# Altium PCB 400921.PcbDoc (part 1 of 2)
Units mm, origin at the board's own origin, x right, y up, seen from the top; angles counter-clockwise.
Board outline 33 x 32.99 mm, 4 copper layers (Top Layer, Mid-Layer 1, Mid-Layer 2, Bottom Layer), stack 0.75 mm thick; 113 components, 68 nets, 329 pads, 369 vias.
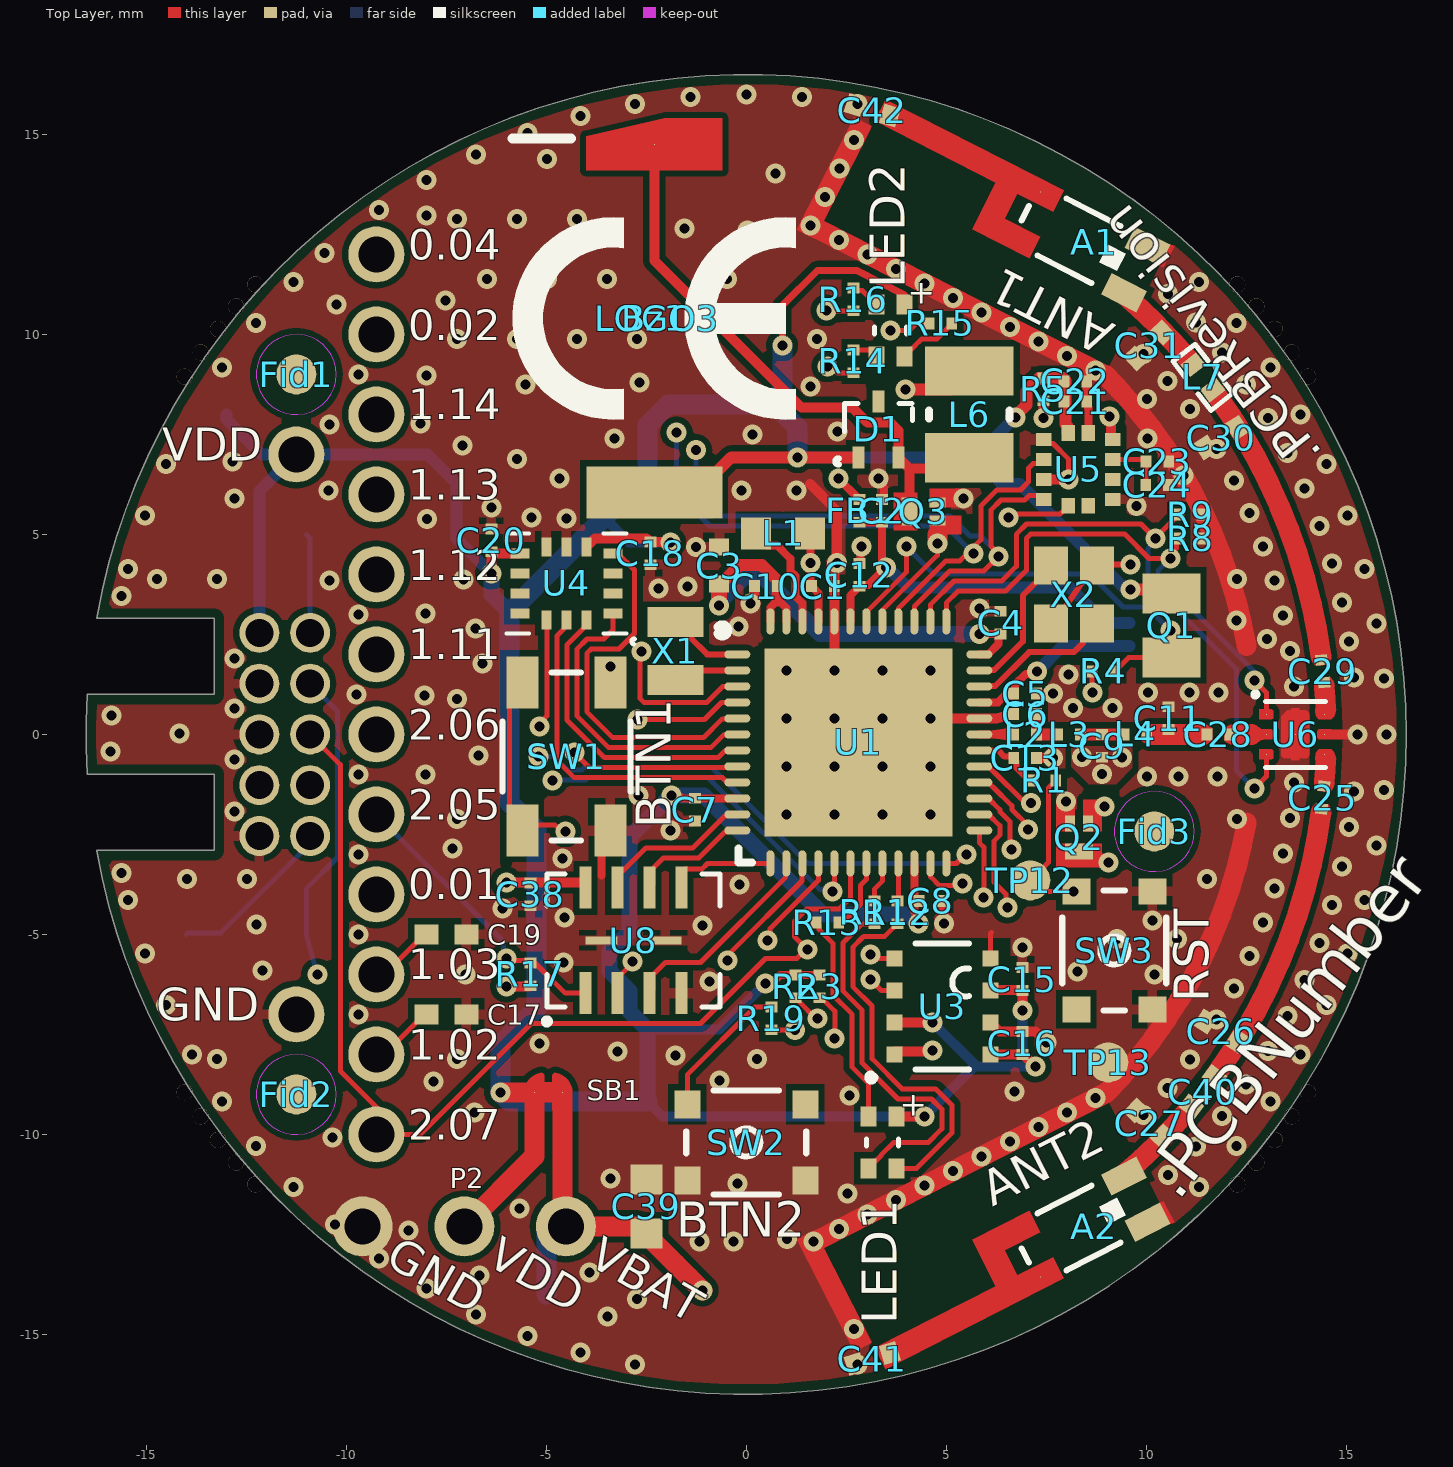
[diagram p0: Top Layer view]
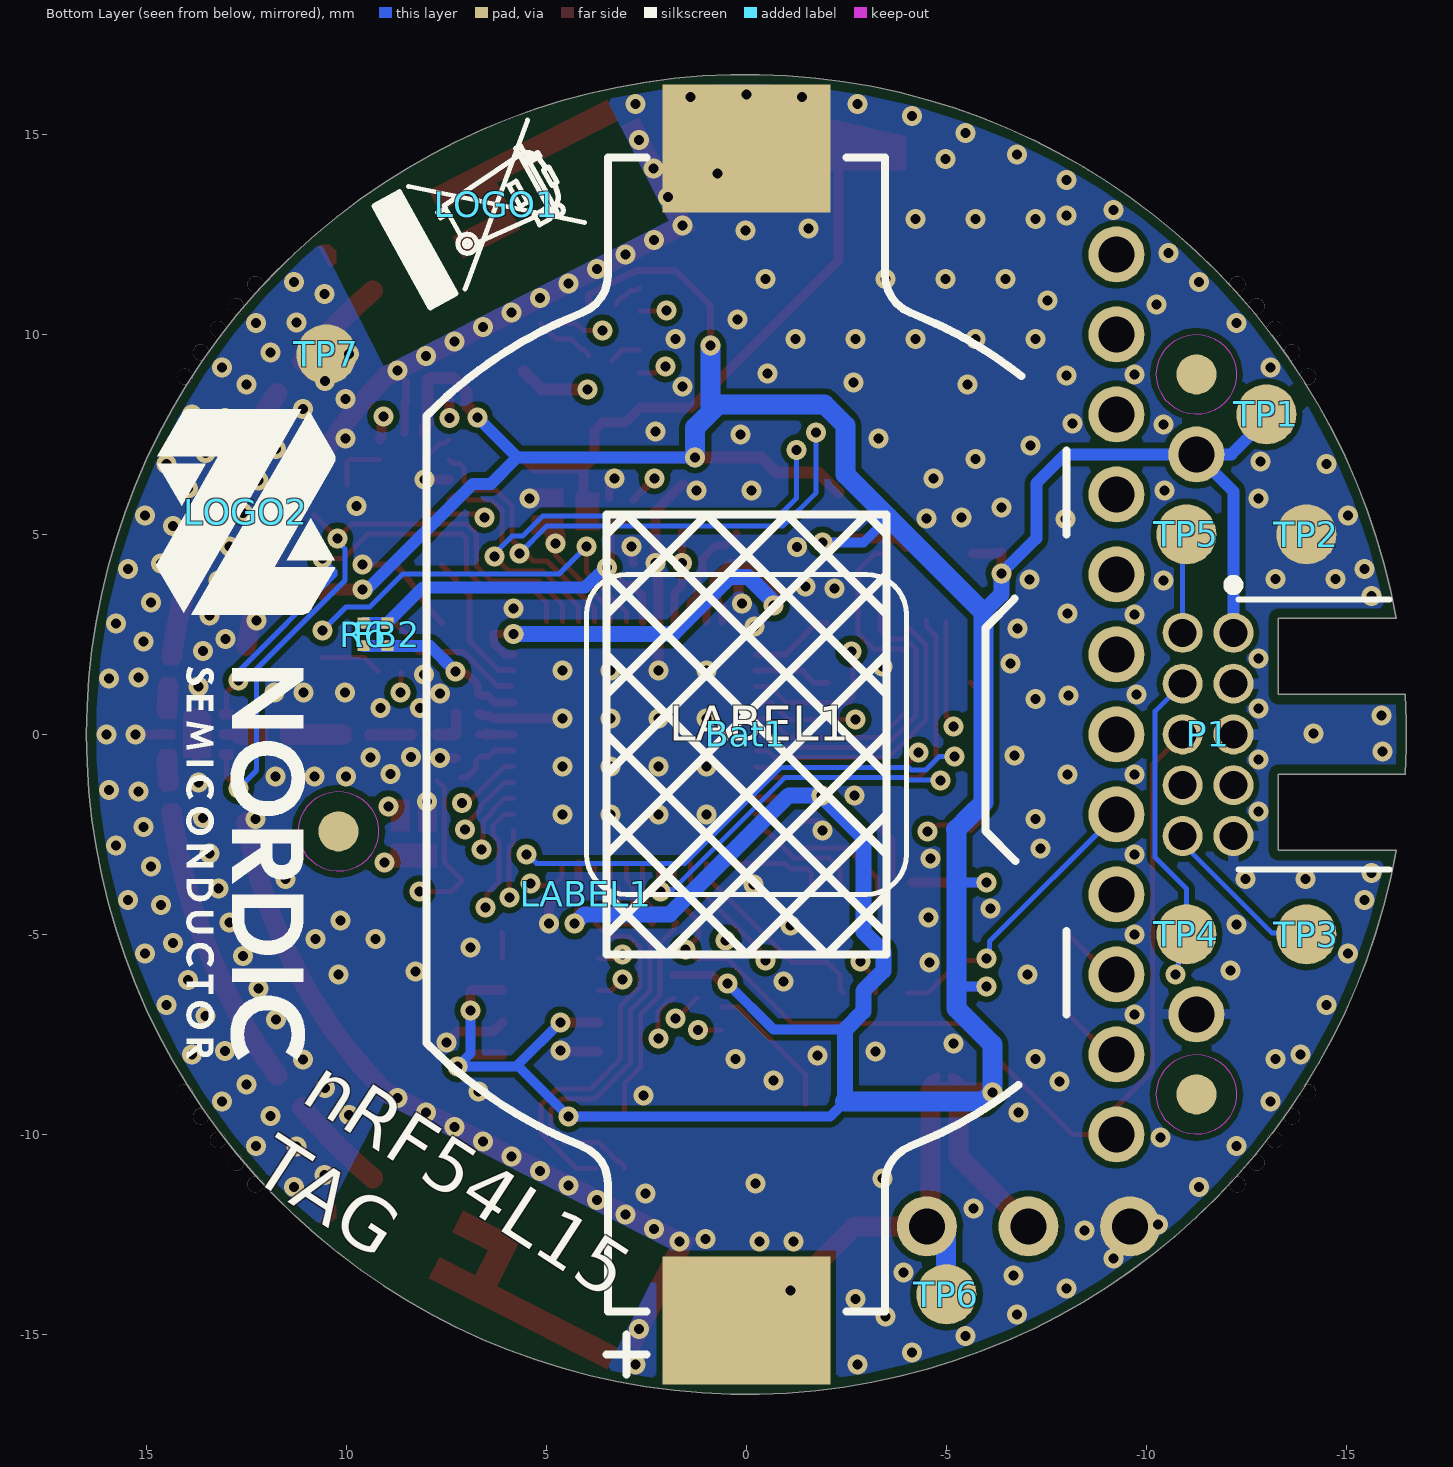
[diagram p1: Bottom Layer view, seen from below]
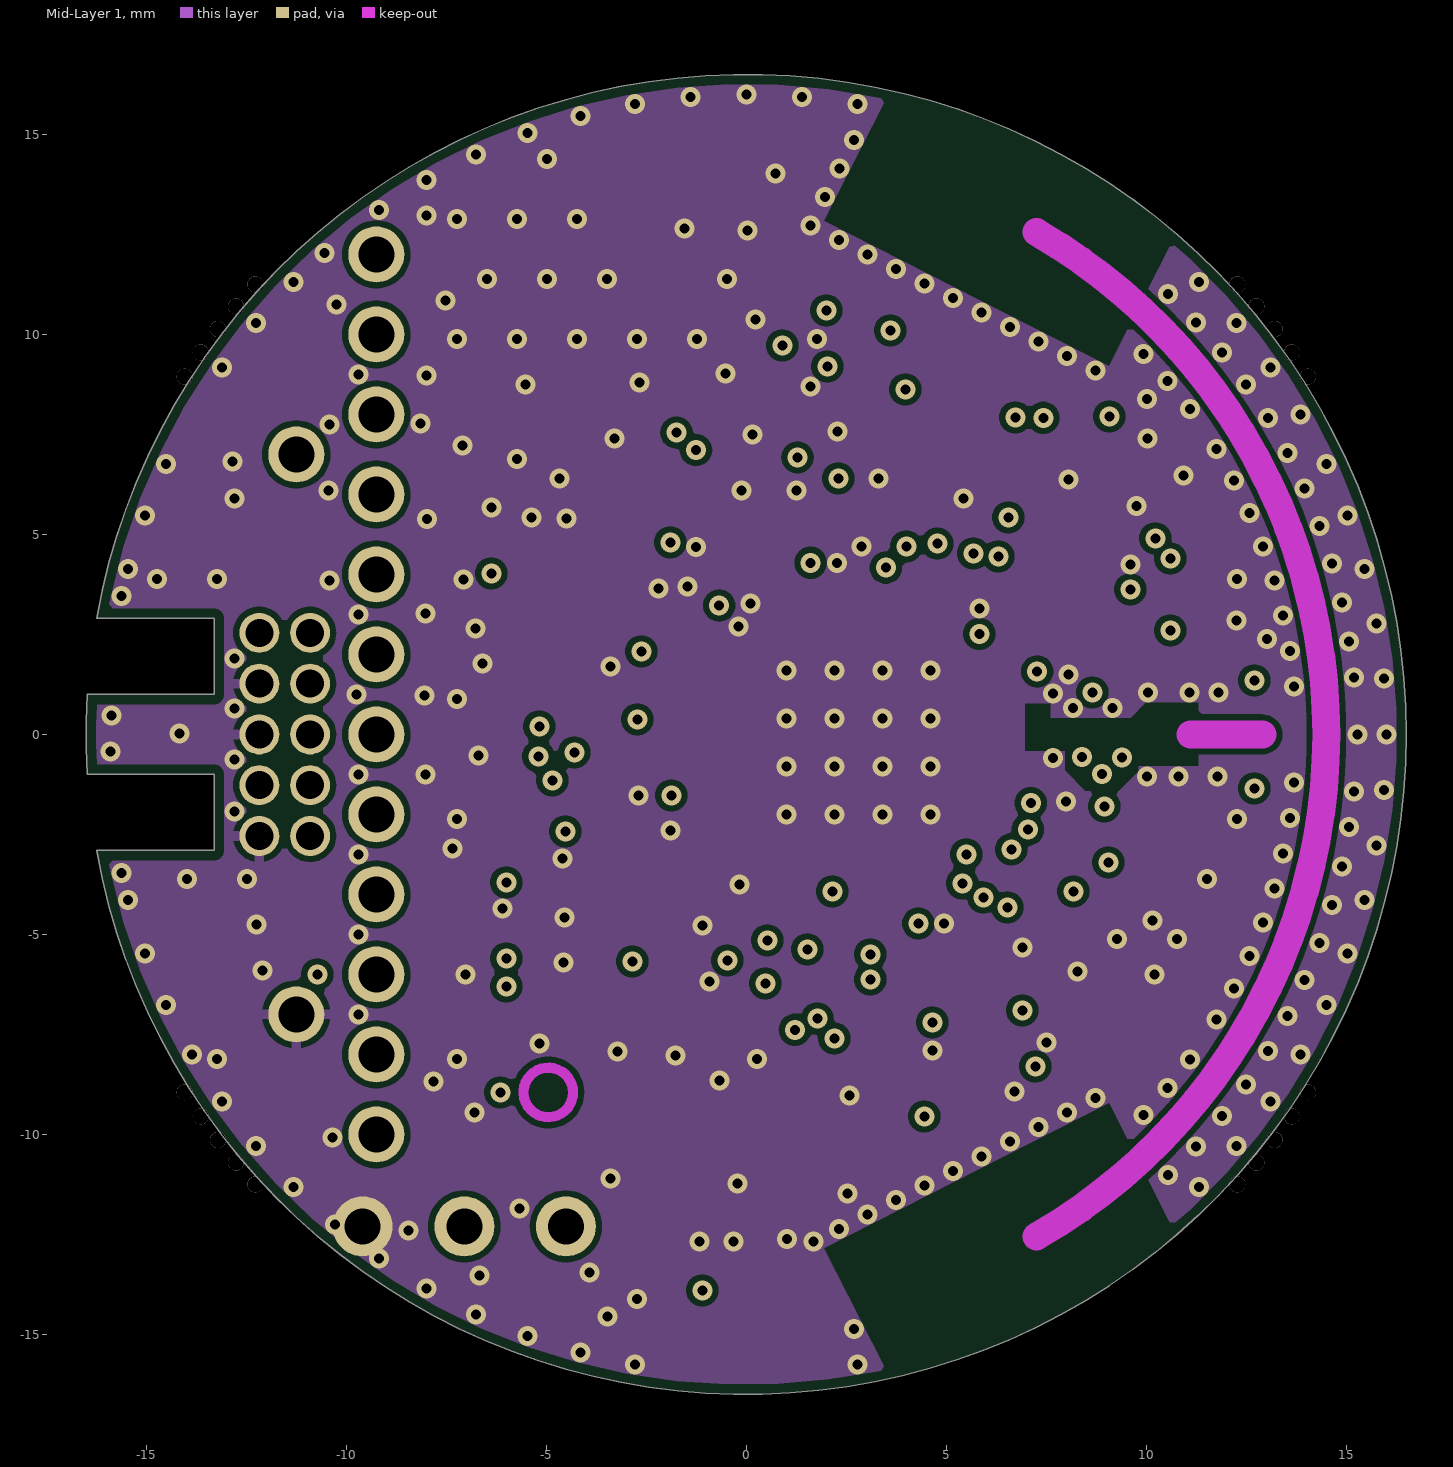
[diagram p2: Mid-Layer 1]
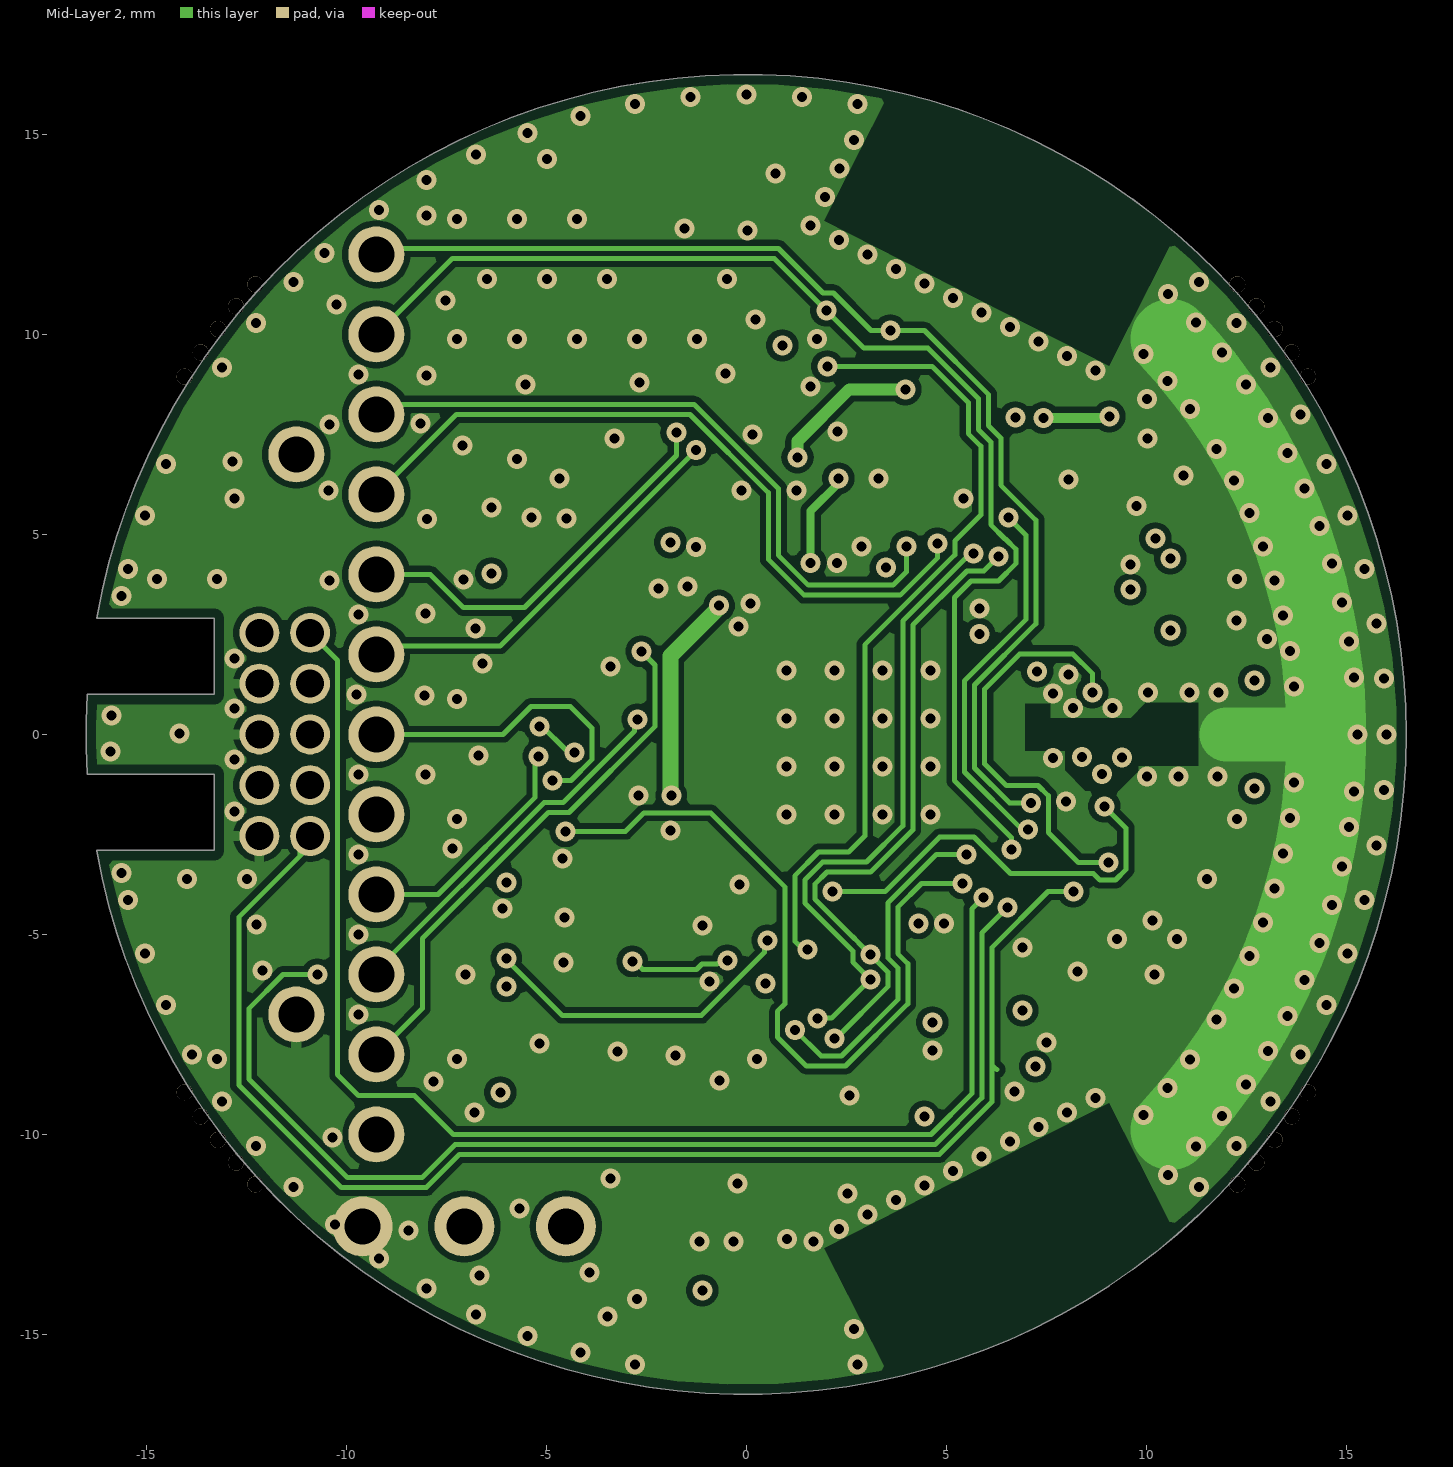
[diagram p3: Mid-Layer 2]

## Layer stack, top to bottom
Top Solder: solder mask 0.0304, Solder Resist Halogen-Free, Dk 3.8
Top Layer: signal copper 0.035
Dielectric1: prepreg 0.09, FR-4 Halogen-Free, Dk 4.2
Mid-Layer 1: signal copper 0.035
Dielectric2: core 0.43, FR-4 Halogen-Free, Dk 4.2
Mid-Layer 2: signal copper 0.035
Dielectric3: prepreg 0.09, FR-4 Halogen-Free, Dk 4.2
Bottom Layer: signal copper 0.035
Bottom Solder: solder mask 0.0304, Solder Resist Halogen-Free, Dk 3.8

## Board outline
-16.47,-1 -13.3,-1 -13.3,-2.9 -16.243,-2.9 ccw(c0,0) -16.243,2.9 -13.3,2.9 -13.3,1 -16.47,1 ccw(c-0.001,0)

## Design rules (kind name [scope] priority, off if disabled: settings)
BoardOutlineClearance BoardOutlineClearance_1 [HasFootprint('L-KLS5-CR2032-23-B1')] p1: gap=0.1 ignorepadtopadclearanceinfootprint=FALSE
BoardOutlineClearance [(OnLayer('Top Layer') OR OnLayer('Mid-Layer 1') OR OnLayer('Mid-Layer 2') OR OnLayer('Bottom Layer'))] p2: gap=0.25 ignorepadtopadclearanceinfootprint=FALSE except(0: Text-OutlineEdge Text-CavityEdge Text-CutoutEdge Text-SplitBarrior Text-SplitContinuation)
Clearance NPTH_Clearance [Not PadIsPlated And OnLayer('Multi-Layer')] p1: gap=0.175 ignorepadtopadclearanceinfootprint=FALSE
Clearance ANT_Clerance [InNet('ANT')] p2: gap=0.127 ignorepadtopadclearanceinfootprint=FALSE except(0: Arc-Hole Track-Hole SMDPad-Hole THPad-Hole Via-Hole Fill-Hole Poly-Hole Region-Hole Text-Hole)
Clearance Polygon_Clearance [(InNamedPolygon('Top_Layer-GND')) or (InNamedPolygon('Bottom_Layer-GND')) or (InNamedPolygon('Mid_Layer_1-GND')) or (InNamedPolygon('Mid_Layer_2-GND'))] p3: gap=0.15 ignorepadtopadclearanceinfootprint=FALSE
Clearance [All] p4: gap=0.125 ignorepadtopadclearanceinfootprint=FALSE
ComponentClearance [All] p1 off: gap=0.254 collisioncheckmode=3 verticalgap=0.254 showdistances=FALSE
DiffPairsRouting [All] p1: maxlimit=0.254 minlimit=0.15 mostfreqgap=0.254 toplayer_maxgap=0.15 toplayer_prefgap=0.15 toplayer_minwidth=0.381 toplayer_maxwidth=0.381 toplayer_prefwidth=0.381 midlayer1_mingap=0.254 midlayer1_minwidth=0.381 midlayer1_maxwidth=0.381 midlayer1_prefwidth=0.381 midlayer2_mingap=0.254 midlayer2_minwidth=0.381 midlayer2_maxwidth=0.381 midlayer2_prefwidth=0.381 bottomlayer_maxgap=0.15 bottomlayer_prefgap=0.15 bottomlayer_minwidth=0.381 bottomlayer_maxwidth=0.381 bottomlayer_prefwidth=0.381 maxuncoupledlength=12.7
FabricationTestPointUsage TestPointUsage [All] p1: valid=0 allowmultiple=FALSE
FabricationTestpoint Testpoint [All] p1: side=3 testpointundercomponent=TRUE minsize=1.016 maxsize=2.54 preferedsize=1.524 minholesize=0 maxholesize=1.016 preferedholesize=0.813 testpointgrid=0.025 allowsidetop=TRUE allowsidebottom=TRUE usegrid=TRUE gridtolerance=0
Height [All] p1 off: minheight=0 maxheight=25.4 prefheight=12.7
HoleSize [All] p1: absolutevalues=TRUE maxlimit=5 minlimit=0.25 maxpercent=80.000 minpercent=20.000
MinimumAnnularRing [All] p1 off: minimumring=0.152
PolygonConnect PolygonConnect_1 [isVia and innet(gnd)] p1: connectstyle=Direct reliefconductorwidth=0.254 reliefentries=4 polygonreliefangle="90 Angle" airgapwidth=0.254
PolygonConnect [All] p2: connectstyle=Relief reliefconductorwidth=0.254 reliefentries=4 polygonreliefangle="90 Angle" airgapwidth=0.15
RoutingVias [All] p1: holewidth=0.25 width=0.5 viastyle="Through Hole" minholewidth=0.2 minwidth=0.4 maxholewidth=0.711 maxwidth=1.27
SilkToSolderMaskClearance SilkscreenOverComponentPads [IsPad] p1: minsilkscreentomaskgap=0.254 clearancetoexposedcopper=TRUE
SolderMaskExpansion SolderMaskExpansion_via [IsVia] p1: expansion=0.076 istentingtop=TRUE
SolderMaskExpansion [All] p2: expansion=0.076 istentingtop=FALSE
SupplyNets "Schematic Supply Nets_9" [InNet('GND')] p1: voltage=0.000
Width Width_RF [InNetClass('RF')] p1: maxlimit=0.517 minlimit=0.076 preferedwidth=0.517 toplayer_minwidth=0.517 midlayer1_maxwidth=0.076 midlayer1_prefwidth=0.078 midlayer2_maxwidth=0.076 midlayer2_prefwidth=0.078 bottomlayer_minwidth=0.517 impedanceprofiledriven=TRUE impedanceprofileid={737E912B-4C07-4FB1-81E6-55882BF422C1} impedanceprofilevalue=50.000000 minimp=50.000000 maximp=50.000000 favimp=50.000000
Width [All] p2: maxlimit=2.54 minlimit=0.125 preferedwidth=0.15
23 further rules are at their usual default settings.

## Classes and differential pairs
net class GPIO: P0.00 P0.01 P0.02 P0.04 P2.07 P2.08 P2.09 P2.10
component class Sensors: C15 C16 C18 C20 C21 C22 C23 C24 Q1 Q2 R2 R3 R4 R5 U3 U4 U5
component class RFFE: A1 A2 C25 C26 C27 C28 C29 C30 C31 C40 C41 C42 L7 R7 R8 R9 U6
component class nRF54L15: 0.01 0.02 0.04 1.02 1.03 1.11 1.12 1.13 1.14 2.05 2.06 2.07 C1 C2 C3 C4 C5 C6 C7 C8 C9 C10 C11 C12 C13 C17 C19 FB1 FB2 GND L1 L2 L3 L4 R1 R6 TP1 TP2 TP3 TP4 TP5 U1 VDD X1 X2
component class Misc: Bat1 Bz1 C38 C39 D1 L6 LED1 LED2 P1 P2 Q3 R11 R12 R13 R14 R15 R16 R17 R19 SB1 SW1 SW2 SW3 TP6 TP7 TP12 TP13 U8
net class SWD_nRF54: P2.07 RESET SWDCLK SWDIO
net class RF: ANT1 ANT2 J1 J2 NetA1_1 NetA2_1 RF RFC
net class QSPI: P2.00 P2.01 P2.02 P2.03 P2.04 P2.05

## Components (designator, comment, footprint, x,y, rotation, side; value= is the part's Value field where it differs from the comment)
0.01 "TP" TESTPAD-TH -9.25,-4 r270 top
0.02 "TP" TESTPAD-TH -9.25,10 r270 top
0.04 "TP" TESTPAD-TH -9.25,12 r270 top
1.02 "TP" TESTPAD-TH -9.25,-8 r270 top
1.03 "TP" TESTPAD-TH -9.25,-6 r270 top
1.11 "TP" TESTPAD-TH -9.25,2 r270 top
1.12 "TP" TESTPAD-TH -9.25,4 r270 top
1.13 "TP" TESTPAD-TH -9.25,6 r270 top
1.14 "TP" TESTPAD-TH -9.25,8 r270 top
2.05 "TP" TESTPAD-TH -9.25,-2 r270 top
2.06 "TP" TESTPAD-TH -9.25,0 r270 top
2.07 "TP" TESTPAD-TH -9.25,-10 r270 top
A1 "2450AT18D0100" 2450AT18D0100_TE-R 8.4,12.3 r333 top
A2 "2450AT18D0100" 2450AT18D0100_TE-L 8.4,-12.3 r207 top
Bat1 "Bat Holder CR2032" L-KLS5-CR2032-23-B1 0,0 r90 bottom locked
Bz1 "Piezo_4kHz" Buzzer_PKMCS0909 -2.3,10.4 r90 top
C1 "2.2µF" CAPC0603X03L_C 1.915,3.709 r180 top
C2 "2.2µF" CAPC0603X03L_C 3.388,5.587 r270 top
C3 "10µF" CAPC1005X04L_C2 -0.677,4.223 r270 top
C4 "100nF" CAPC0603X03L_C 6.358,2.793 r90 top
C5 "100pF" CAPC0603X03L_C 6.968,1.019 r180 top
C6 "1.5pF" CAPC0603X03L_C 6.968,0.507 r0 top
C7 "100nF" CAPC0603X03L_C -1.287,-1.881 r270 top
C8 "100nF" CAPC0603X03L_C 4.604,-4.162 r0 top
C9 "2.0pF" CAPC0603X03L_C 8.898,-0.286 r90 top
C10 "100nF" CAPC0603X03L_C 0.491,3.707 r180 top
C11 "0.3pF" CAPC0603X03L_C 10.549,0.405 r270 top
C12 "18pF" CAPC0603X03L_C 2.828,3.987 r270 top
C13 "3.9pF" CAPC0603X03L_C 6.973,-0.586 r180 top
C15 "100nF" CAPC0603X03L_C 6.9,-6.115 r270 top
C16 "100nF" CAPC0603X03L_C 6.9,-7.715 r270 top
C17 "TBD" CAPC1005X04L -7.5,-7 r0 top
C18 "100nF" CAPC0603X03L_C -2.4,4.525 r90 top
C19 "TBD" CAPC1005X04L -7.5,-5 r0 top
C20 "100nF" CAPC0603X03L_C -6.375,4.85 r270 top
C21 "100nF" CAPC0603X03L_C 8.225,8.325 r180 top
C22 "100nF" CAPC0603X03L_C 8.225,8.825 r180 top
C23 "100nF" CAPC0603X03L_C 10.275,6.825 r180 top
C24 "100nF" CAPC0603X03L_C 10.273,6.24 r180 top
C25 "47pF" CAPC0603X03L_C 14.414,-1.579 r83.75 top
C26 "0.8pF" CAPC1005X04L_C2 11.873,-7.419 r328 top
C27 "N.C." CAPC1005X04L_C2 10.071,-9.725 r316 top
C28 "47pF" CAPC0603X03L_C 11.8,0 r180 top
C29 "47pF" CAPC0603X03L_C 14.414,1.579 r276.25 top
C30 "1.2pF" CAPC1005X04L_C2 11.873,7.419 r32 top
C31 "N.C." CAPC1005X04L_C2 10.071,9.725 r44 top
C38 "100nF" CAPC0603X03L_C -5.4,-4 r270 top
C39 "47µF" CAPC1608X06L -2.5,-11.8 r270 top
C40 "6.8pF" CAPC1005X04L_C2 11.416,-8.927 r232 top
C41 "2.0pF" CAPC1005X04L_C2 3.149,-15.603 r17 top
C42 "1.5pF" CAPC1005X04L_C2 3.149,15.603 r343 top
D1 "BZB984-C12,115" SOTFL50P160X60-3L 3.3,7.625 r90 top
FB1 "120R/0.2A" INDC0603X03L_C 2.828,5.587 r270 top
FB2 "120R/0.2A" INDC0603X03L_C 8.975,2.5 r90 bottom
Fid1 "Fiducial mark" Fiducial -11.25,9 r180 top value=N.A.
Fid2 "Fiducial mark" Fiducial -11.25,-9 r180 top value=N.A.
Fid3 "Fiducial mark" Fiducial 10.2,-2.425 r180 top value=N.A.
GND "TP" TESTPAD-TH -11.25,-7 r270 top
L1 "4.7µH" INDC1608X06L 0.923,5.028 r0 top
L2 "2.7nH" INDC0603X03L_C 6.968,-0.001 r0 top
L3 "3.5nH" INDC0603X03L_C 8.07,-0.001 r0 top
L4 "3.5nH" INDC0603X03L_C 9.726,-0.001 r0 top
L6 "1.0mH" INDC2520X10N 5.575,8 r90 top
L7 "2.7nH" INDC1005X04L_C2 11.416,8.927 r128 top
LABEL1 "8x8mm" LabelSilk_8x8 4,-4 r180 bottom
LED1 "LED RGB" LED_RGB_0603 3.4,-10.2 r180 top
LED2 "LED RGB" LED_RGB_0603 3.6,10.1 r180 top
LOGO1 "WEE Symbol" WEEE_3x4.5mm 6.25,13.25 r241 bottom
LOGO2 "Nordic Logo" NORDIC_LOGO_LYING 12.512,5.563 r270 bottom
LOGO3 "CE Logo" CE_logo -2.241,10.4 r0 top
P1 "Socket 2x5, Angled" SOCKET_ANG_2x5_TH-1.27mm -14.45,0 r90 bottom
P2 "Pin List 1x3" LIST_1x3-NC -7.05,-12.3 r180 top
Q1 "TEMT6200FX01" TEMT6200FX01 10.625,2.725 r90 top
Q2 "RV2C010UNT2L" DFN65P100X40-3L 8.312,-2.575 r270 top
Q3 "RV2C010UNT2L" DFN65P100X40-3L 4.425,5.575 r180 top
R1 "1k" RESC0603X03L_C 7.451,-1.152 r0 top
R2 "10k" RESC0603X03L_C 1.225,-6.3 r90 top
R3 "10k" RESC0603X03L_C 1.825,-6.3 r90 top
R4 "2k7" RESC0603X03L_C 8.925,1.575 r0 top
R5 "10R" RESC0603X03L_C 7.425,8.625 r270 top
R6 "4R7" RESC0603X03L_C 9.575,2.5 r90 bottom
R8 "1M0" RESC0603X03L_C 11.1,4.9 r180 top
R9 "1M0" RESC0603X03L_C 11.1,5.5 r180 top
R11 "390R" RESC0603X03L_C 3.2,-4.45 r270 top
R12 "2k2" RESC0603X03L_C 3.775,-4.45 r270 top
R13 "1k2" RESC0603X03L_C 2.025,-4.7 r180 top
R14 "390R" RESC0603X03L_C 2.675,9.325 r90 top
R15 "2k2" RESC0603X03L_C 4.85,10.275 r0 top
R16 "1k2" RESC0603X03L_C 2.675,10.875 r90 top
R17 "100k" RESC0603X03L_C -5.4,-6 r270 top
R19 "0R" RESC0603X03L_C 0.625,-7.1 r270 top
SB1 "Solderbridge" Solderbridge_Shorted_Power -4.95,-8.95 r180 top net-tie
SW1 "PB SW" KLS-TS3402 -4.5,-0.55 r270 top locked
SW2 "PB SW" SW_TACTILE_2.6x3.0MM_4-LEAD 0,-10.2 r0 top
SW3 "PB SW" SW_TACTILE_2.6x3.0MM_4-LEAD 9.2,-5.4 r270 top
TP1 "Ø1.5mm,SMD" TP_SMD_D1.5mm -13,8 r270 bottom
TP2 "Ø1.5mm,SMD" TP_SMD_D1.5mm -14,5 r180 bottom
TP3 "Ø1.5mm,SMD" TP_SMD_D1.5mm -14,-5 r180 bottom
TP4 "Ø1.5mm,SMD" TP_SMD_D1.5mm -11,-5 r180 bottom
TP5 "Ø1.5mm,SMD" TP_SMD_D1.5mm -11,5 r180 bottom
TP6 "Ø1.5mm,SMD" TP_SMD_D1.5mm -5,-14 r180 bottom
TP7 "Ø1.5mm,SMD" TP_SMD_D1.5mm 10.5,9.5 r180 bottom
TP12 "Ø1.0mm,SMD" TP_SMD_D1.0mm 7.1,-3.65 r0 top
TP13 "Ø1.0mm,SMD" TP_SMD_D1.0mm 9.05,-8.2 r0 top
U1 "nRF54L15-QFAA-C00" QFN40P600X600X90-48N 2.8,-0.2 r0 top
U3 "BME688" BME680 4.9,-6.8 r180 top
U4 "BMI270" BMI270 -4.5,3.775 r180 top
U5 "ADXL367" LGA50P220X230X97-12N 8.3,6.625 r0 top
U6 "SKY13348-374LF" SON50P150X50_HS-7N 13.725,0 r0 top
U8 "MX25R6435F" SON80P300X60_HS-9N -2.825,-5.15 r90 top
VDD "TP" TESTPAD-TH -11.25,7 r270 top
X1 "32.768kHz" XTAL_2012 -1.774,2.08 r90 top
X2 "32MHz" BT-XTAL_2016 8.187,3.504 r90 top

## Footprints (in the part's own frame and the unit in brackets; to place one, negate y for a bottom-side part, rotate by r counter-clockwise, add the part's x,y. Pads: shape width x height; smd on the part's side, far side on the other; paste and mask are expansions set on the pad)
2450AT18D0100_TE-L [mm] "2450MHz Antenna"
  rect 1x0.6 smd mask+0.05: 1(-1.5,-0.65) 2(-1.5,0.65)
  round 0.025 smd paste-5 mask+0.051: 3(1.5,0.65)
  Top Layer region: 6,0.95 1,0.95 1,0.35 2,0.35 2,-0.35 1,-0.35 1,-0.95 2.6,-0.95 2.6,0.35 6,0.35
  Multi-Layer pour cut-out: -2,-2.45 -2,1.5 6,1.5 6,-2.45
  silkscreen extent -1.1,-0.8 1.6,0.8, body extent -1.61,-0.81 1.61,0.81, height 1.2
2450AT18D0100_TE-R [mm] "2450MHz Antenna"
  rect 1x0.6 smd mask+0.05: 1(1.5,-0.65) 2(1.5,0.65)
  round 0.025 smd paste-5 mask+0.051: 3(-1.5,0.65)
  Top Layer region: -6,0.95 -1,0.95 -1,0.35 -2,0.35 -2,-0.35 -1,-0.35 -1,-0.95 -2.6,-0.95 -2.6,0.35 -6,0.35
  Multi-Layer pour cut-out: 2,-2.45 2,1.5 -6,1.5 -6,-2.45
  silkscreen extent -1.6,-0.8 1.1,0.8, body extent -1.61,-0.81 1.61,0.81, height 1.2
BME680 [mm]
  rect 0.4x0.4 smd mask+0.1: 1(1.2,1.2) 2(1.2,0.4) 3(1.2,-0.4) 4(1.2,-1.2) 5(-1.2,-1.2) 6(-1.2,-0.4) 7(-1.2,0.4) 8(-1.2,1.2)
  silkscreen extent -0.67,-1.58 1.82,1.82, body extent -1.5,-1.5 1.5,1.5, height 0.93
BMI270 [mm] "Description 6-axis, smart, low-power, inertial measurement unit"
  rect 0.475x0.25 smd: 1(-1.163,0.75) 2(-1.162,0.25) 3(-1.162,-0.25) 4(-1.162,-0.75) 8(1.162,-0.75) 9(1.162,-0.25) 10(1.162,0.25) 11(1.162,0.75)
  rect 0.25x0.475 smd: 5(-0.5,-0.913) 6(0,-0.913) 7(0.5,-0.913) 12(0.5,0.912) 13(0,0.912) 14(-0.5,0.912)
  silkscreen extent -1.71,-1.25 1.5,1.51, body extent -1.5,-1.25 1.5,1.25, height 0.7
BT-XTAL_2016 [mm] "Crystal 2.0 x 1.6 mm"
  rect 0.95x0.85 smd: 1(-0.725,-0.575) 2(0.725,-0.575) 3(0.725,0.575) 4(-0.725,0.575)
  body extent -1.05,-0.85 1.05,0.85, height 0.56
Buzzer_PKMCS0909 [mm]
  rect 1.3x3.4 smd: 1(-4.35,0)
  round 0.025 smd: 2(4.35,0)
  Top Layer region: 3.7,1.7 3.7,-1.7 5,-1.7 5,-0.25 4.55,1.7
  silkscreen extent 4.5,2.08 4.5,3.55, body extent -4.5,-4.5 4.5,4.5, height 1.9
CAPC0603X03L_C [mm] "Chip Capacitor, 2-Leads, Body 0.6x0.3mm, IPC High Density"
  rect 0.27x0.3 smd mask+0.05: 1(-0.285,0) 2(0.285,0)
  body extent -0.3,-0.15 0.3,0.15, height 0.3
CAPC1005X04L [mm] "Chip Capacitor, 2-Leads, Body 1.0x0.5mm, IPC High Density"
  rect 0.6x0.5 smd: 1(-0.5,0) 2(0.5,0)
  body extent -0.5,-0.25 0.5,0.25, height 0.5
CAPC1005X04L_C2 [mm] "Chip Capacitor, 2-Leads, Body 1.0x0.5mm, IPC High Density"
  rect 0.425x0.5 smd mask+0.05: 1(-0.463,0) 2(0.463,0)
  body extent -0.5,-0.25 0.5,0.25, height 0.5
CAPC1608X06L [mm] "Chip Capacitor, 2-Leads, Body 1.6x0.8mm, IPC High Density"
  rect 0.75x0.8 smd: 1(-0.675,0) 2(0.675,0)
  body extent -0.8,-0.4 0.8,0.4, height 0.8
CE_logo [mm]
  silkscreen extent -3.6,-2.53 3.48,2.53
DFN65P100X40-3L [mm] "DFN, 3-Leads, Body 0.60x1.00mm, Pitch 0.65mm, IPC High Density"
  rect 0.4x0.25 smd mask+0.05: 1(-0.35,0.225) 2(-0.35,-0.225)
  rect 0.4x0.7 smd mask+0.065: 3(0.35,0)
  body extent -0.53,-0.32 0.53,0.32, height 0.4
Fiducial [mm] "Fiducial Mark"
  round 1 smd paste-2539.97 mask+0.5: 0(0,0)
  round 1 smd far side paste-2539.97 mask+0.5: 0(0,0)
  Top Layer keep-out circle w0.01: c0,0 r1
  Bottom Layer keep-out circle w0.01: c0,0 r1
INDC0603X03L_C [mm] "Chip Inductor, 2-Leads, Body 0.6x0.3mm, IPC High Density"
  rect 0.27x0.3 smd: 1(-0.285,0) 2(0.285,0)
  body extent -0.3,-0.15 0.3,0.15, height 0.3
INDC1005X04L_C2 [mm] "Chip Inductor, 2-Leads, Body 1.0x0.5mm, IPC High Density"
  rect 0.4x0.5 smd mask+0.05: 1(-0.4,0) 2(0.4,0)
  silkscreen extent -0.78,-0.35 0.77,0.35, body extent -0.5,-0.25 0.5,0.25, height 0.5
INDC1608X06L [mm] "Chip Inductor, 2-Leads, Body 1.6x0.8mm, IPC High Density"
  rect 0.75x0.8 smd: 1(-0.675,0) 2(0.675,0)
  body extent -0.8,-0.4 0.8,0.4, height 0.8
INDC2520X10N [mm] "Chip Inductor, 2-Leads, Body 2,50x2,00mm, IPC Medium Density"
  rect 1.23x2.22 smd: 1(-1.085,0) 2(1.085,0)
  silkscreen extent -0.1,-1.01 0.1,1.01, body extent -1.25,-1 1.25,1, height 1.2
KLS-TS3402 [mm] "Microminiature SMT Top Actuated"
  rect 1.3x0.8 smd: 1(-1.85,1.1) 1(1.85,1.1) 2(-1.85,-1.1) 2(1.85,-1.1)
  silkscreen extent -2.1,-1.6 2.1,1.6, body extent -2.29,-1.6 2.29,1.6, height 2.5
L-KLS5-CR2032-23-B1 [mm] "SMT,CR2032 Coin Battery Holder"
  rect 3.2x4.2 smd: 1(-14.65,0) 2(14.65,0)
  silkscreen extent -16,-8 14.42,8, body extent -15.7,-8 15.85,8, height 5.17
LabelSilk_8x8 [mm] "PCA version label, stick-on, 8mmx8mm"
  silkscreen extent 0,0 8,8, body extent 0,0 8,8, height 0.05
LED_RGB_0603 [mm]
  rect 0.4x0.5 smd paste+0: 1(0.35,-0.65) 2(-0.35,0.65) 3(0.35,0.65) 4(-0.35,-0.65)
  silkscreen extent -0.4,-0.08 0.4,0.08, body extent -0.4,-0.8 0.4,0.8, height 0.5
LGA50P220X230X97-12N [mm] "LGA, 12-Leads, Body 2,20x2,30mm, Pitch 0,50mm, IPC Medium Density"
  rect 0.39x0.33 smd mask+0.05: 1(-0.86,0.75) 2(-0.86,0.25) 3(-0.86,-0.25) 4(-0.86,-0.75) 7(0.86,-0.75) 8(0.86,-0.25) 9(0.86,0.25) 10(0.86,0.75)
  rect 0.33x0.39 smd mask+0.05: 5(-0.25,-0.91) 6(0.25,-0.91) 11(0.25,0.91) 12(-0.25,0.91)
  body extent -1.15,-1.2 1.15,1.2, height 0.97
LIST_1x3-NC [mm] "Pin List, 2.54mm through hole"
  round 1.5 hole 0.9: 1(-2.54,0) 2(0,0) 3(2.54,0)
NORDIC_LOGO_LYING [mm]
  silkscreen extent -2.57,-2.24 13.7,2.24
QFN40P600X600X90-48N [mm] "QFN, 48-Leads, Body 6,0x6,0mm (max), Pitch 0,40mm, IPC Medium Density"
  oval 0.65x0.2 smd: 1(-3.025,2.2) 2(-3.025,1.8) 3(-3.025,1.4) 4(-3.025,1) 5(-3.025,0.6) 6(-3.025,0.2) 7(-3.025,-0.2) 8(-3.025,-0.6) 9(-3.025,-1) 10(-3.025,-1.4) 11(-3.025,-1.8) 12(-3.025,-2.2) 25(3.025,-2.2) 26(3.025,-1.8) 27(3.025,-1.4) 28(3.025,-1) 29(3.025,-0.6) 30(3.025,-0.2) 31(3.025,0.2) 32(3.025,0.6) 33(3.025,1) 34(3.025,1.4) 35(3.025,1.8) 36(3.025,2.2)
  oval 0.2x0.65 smd: 13(-2.2,-3.025) 14(-1.8,-3.025) 15(-1.4,-3.025) 16(-1,-3.025) 17(-0.6,-3.025) 18(-0.2,-3.025) 19(0.2,-3.025) 20(0.6,-3.025) 21(1,-3.025) 22(1.4,-3.025) 23(1.8,-3.025) 24(2.2,-3.025) 37(2.2,3.025) 38(1.8,3.025) 39(1.4,3.025) 40(1,3.025) 41(0.6,3.025) 42(0.2,3.025) 43(-0.2,3.025) 44(-0.6,3.025) 45(-1,3.025) 46(-1.4,3.025) 47(-1.8,3.025) 48(-2.2,3.025)
  rect 4.7x4.7 smd: 49(0,0)
  silkscreen extent -3.49,-3 -2.65,2.92, body extent -3.02,-3.02 3.02,3.02, height 0.86
RESC0603X03L_C [mm] "Chip Resistor, 2-Leads, Body 0.6x0.3mm, IPC High Density"
  rect 0.27x0.3 smd: 1(-0.285,0) 2(0.285,0)
  body extent -0.3,-0.15 0.3,0.15, height 0.23
SOCKET_ANG_2x5_TH-1.27mm [mm] "CONN SOCKET RIGHT ANGLE DUAL 10POS - SOCKET, PCB, 0.05\", 5+5WAY"
  round 1 hole 0.7 paste-2539.97: 1(2.54,2.275) 2(2.54,3.545) 3(1.27,2.275) 4(1.27,3.545) 5(0,2.275) 6(0,3.545) 7(-1.27,2.275) 8(-1.27,3.545) 9(-2.54,2.275) 10(-2.54,3.545)
  silkscreen extent -3.37,-1.63 3.86,2.4, body extent -3.37,-2.15 3.37,3.62, height 3.1
Solderbridge_Shorted_Power [mil]
  round 1 smd paste-99999: 1(-13.84,0.21) 2(13.72,0.21)
  Top Layer region: -4.92,9.84 4.92,9.84 4.92,-9.84 -4.92,-9.84
  Top Layer region: -7.54,19.57 -15.82,15.94 -21.61,9 -23.68,0.21 -23.68,0.21 -21.61,-8.59 -15.82,-15.53 -7.54,-19.16 -7.54,-19.16 -6.24,-19.11 -5.08,-18.51 -4.28,-17.47 -4,-16.2 -3.99,-16.2 -3.99,16.61 -4.28,17.89 -5.08,18.92 -6.24,19.52 -7.54,19.57
  Top Layer region: 7.43,-19.16 15.71,-15.53 21.49,-8.59 23.56,0.21 23.56,0.21 21.49,9 15.71,15.94 7.43,19.57 7.43,19.57 6.12,19.52 4.96,18.92 4.16,17.89 3.88,16.61 3.88,16.61 3.88,-16.2 4.16,-17.47 4.96,-18.51 6.12,-19.11 7.43,-19.16
SON50P150X50_HS-7N [mil] "SON, 6-Leads, Body 1,50x1,50mm, Pitch 0,50mm, Thermal Pad 1,20x0,58mm, IPC Medium Density"
  round 1 smd mask+1.97: 1(-28.54,19.69) 2(-28.54,0) 3(-28.54,-19.69) 4(28.54,-19.69) 5(28.54,0) 6(28.54,19.69) 7(0,0)
  Top Layer region: 9.64,-23.62 3.94,-23.62 3.94,-25.62 -3.94,-25.59 -3.94,-23.62 -9.65,-23.62 -11.23,-23.31 -12.57,-22.41 -13.47,-21.07 -13.78,-19.49 -13.78,-19.49 -13.78,17.81 -7.77,23.62 -3.94,23.62 -3.94,25.59 3.94,25.59 3.94,23.62 9.65,23.62 11.23,23.31 12.57,22.41 13.47,21.07 13.78,19.49 13.78,19.49 13.78,-19.49 13.47,-21.07 12.57,-22.41 11.23,-23.31 9.64,-23.62
  Top Layer region: -35.43,14.76 -35.43,24.61 -24.11,24.61 -23.17,24.42 -22.37,23.89 -21.84,23.09 -21.65,22.15 -21.65,22.15 -21.65,17.22 -21.84,16.28 -22.37,15.48 -23.17,14.95 -24.11,14.76 -24.11,14.76
  Top Layer region: -35.43,-4.92 -35.43,4.92 -24.11,4.92 -23.17,4.73 -22.37,4.2 -21.84,3.4 -21.65,2.46 -21.65,2.46 -21.65,-2.46 -21.84,-3.4 -22.37,-4.2 -23.17,-4.73 -24.11,-4.92 -24.11,-4.92
  Top Layer region: -35.43,-24.61 -35.43,-14.76 -24.11,-14.76 -23.17,-14.95 -22.37,-15.48 -21.84,-16.28 -21.65,-17.22 -21.65,-17.22 -21.65,-22.15 -21.84,-23.09 -22.37,-23.89 -23.17,-24.42 -24.11,-24.61 -24.11,-24.61
  Top Layer region: 35.43,24.61 35.43,14.76 24.11,14.76 23.17,14.95 22.37,15.48 21.84,16.28 21.65,17.22 21.65,17.22 21.65,22.15 21.84,23.09 22.37,23.89 23.17,24.42 24.11,24.61 24.11,24.61
  Top Layer region: 35.43,4.92 35.43,-4.92 24.11,-4.92 23.17,-4.73 22.37,-4.2 21.84,-3.4 21.65,-2.46 21.65,-2.46 21.65,2.46 21.84,3.4 22.37,4.2 23.17,4.73 24.11,4.92 24.11,4.92
  Top Layer region: 35.43,-14.76 35.43,-24.61 24.11,-24.61 23.17,-24.42 22.37,-23.89 21.84,-23.09 21.65,-22.15 21.65,-22.15 21.65,-17.22 21.84,-16.28 22.37,-15.48 23.17,-14.95 24.11,-14.76 24.11,-14.76
  silkscreen extent -41,-32 30,41, body extent -30,-30 30,30, height 20
SON80P300X60_HS-9N [mm] "SON, 8-Leads, Body 4,00x3,00mm, Pitch 0,80mm, Thermal Pad 0,80x0,20mm, IPC Medium Density"
  rect 1.05x0.3 smd: 1(-1.32,1.2) 2(-1.32,0.4) 3(-1.32,-0.4) 4(-1.32,-1.2) 5(1.32,-1.2) 6(1.32,-0.4) 7(1.32,0.4) 8(1.32,1.2)
  rect 0.2x0.8 smd: 9(0,0.8) 9(0,-0.8)
  silkscreen extent -2.07,-2.16 1.66,2.21, body extent -1.55,-2.05 1.55,2.05, height 0.6
SOTFL50P160X60-3L [mm] "SOTFL, 3-Leads, Body 1.60x1.60mm, Pitch 0.50mm, IPC High Density"
  rect 0.55x0.3 smd: 1(-0.7,0.5) 2(-0.7,-0.5) 3(0.7,0)
  silkscreen extent -0.87,-0.85 0.65,1.08, body extent -0.8,-0.85 0.8,0.85, height 0.6
SW_TACTILE_2.6x3.0MM_4-LEAD [mm] "2.6×3.0mm TACT Switch, without ground connector"
  rect 0.65x0.7 smd: 1(-1.475,0.95) 1(1.475,0.95) 2(-1.475,-0.95) 2(1.475,-0.95)
  silkscreen extent -1.5,-1.3 1.5,1.3, body extent -1.6,-1.3 1.6,1.3, height 0.65
TEMT6200FX01 [mm] "Chip Diode, 2-Leads, Body 2,00x1,25mm, IPC Medium Density"
  rect 1x1.45 smd: C(0.8,0) E(-0.8,0)
  body extent -1,-0.63 1,0.63, height 0.85
TESTPAD-TH [mm]
  round 1.4 hole 0.9: 1(0,0)
TP_SMD_D1.0mm [mm] "Test point - pad 1.0mm"
  round 1 smd paste-5: 1(0,0)
TP_SMD_D1.5mm [mm] "Test point - pad 1.5mm"
  round 1.5 smd paste-5: 1(0,0)
  body extent -0.75,-0.75 0.75,0.75, height 0.05
WEEE_3x4.5mm [mm]
  silkscreen extent -1.47,-2.7 1.47,1.71
XTAL_2012 [mm] "XTAL SMD 2.0 x 1.2 mm"
  rect 0.75x1.4 smd: 1(-0.725,0) 2(0.725,0)
  body extent -1,-0.61 1,0.61, height 0.6

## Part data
0.01 0.02 0.04 1.02 1.03 1.11 1.12 1.13 1.14 2.05 2.06 2.07 GND VDD: library part "Testpoint TH", "Testpoint, through hole", Manufacturer=N.A., Part number NEMS=100500464
A1 A2: library part "Johanson 2450AT18D0100_TE", "2.45 GHz chip antenna", Manufacturer="Johanson Technology", Part number IPS=00000001415, Part number NEMS="100700004, 100700005, 100700006", Part number Norautron=N.A., Supplier Part Number 1=2450AT18D0100E
Bat1: library part "Bat Holder L-KLS5-CR2032-23-BR", "Bat Holder CR2032 SMD", Manufacturer="KLS Electronic", Manufacturer Part Number=L-KLS5-CR2032-23-BR, Part number IPS=N.A., Part number NEMS=100500651
Bz1: library part PKMCS0909E4000-R1, "Piezo Buzzer, SMD, 9.0mm x 9.0mm x 1.9mm, 4kHz, 65dB @ 1.5V, <12.5Vp-p", Manufacturer=Murata, Part number IPS=N.A., Part number NEMS=101000026, Supplier Part Number 1=490-9647-1-ND
C1 C2: library part C0201-2µ2-2.5V-X6T-GRM033D80E225ME47D, "Capacitor, Ceramic, 2.2µF 2.5V X6T 0201,±20%", Manufacturer=Murata, Manufacturer Part Number=GRM033D80E225ME47D, Part number IPS=N.A., Part number NEMS=100200527, Supplier Part Number 1=81-GRM033D80E225ME7D
C3: library part C0402-10µ-6.3V-X5R-GRM155R60J106ME05D, "Capacitor, X5R, ±20%, 6.3V", Manufacturer=Murata, Manufacturer Part Number=GRM155R60J106ME05D, Part number IPS=N.A., Part number NEMS=100200554, Supplier Part Number 1=490-GRM155R60J106ME05DTR-ND
C4 C7 C8 C10 C15 C16 C18 C20 C21 C22 C23 C24 C38: library part C0201-100n, "Capacitor, X5R, ±10%, 100nF, 16V", Manufacturer=N.A., Part number IPS="00000001248, 00000002505", Part number NEMS=100200078, Part number Norautron=262071862
C5: library part C0201-100p, "Capacitor, NP0, ±2%, 25V", Manufacturer=Murata, Manufacturer Part Number=GRM0335C1E101GA01D, Part number IPS=00000007853, Part number NEMS=100200044, Part number Norautron=N.A.
C6: library part C0201-1.5p-25V-NP0-GJM0335C1E1R5WB01, "Capacitor, NP0, ±0.05pF, 25V, High Q", Manufacturer=Murata, Manufacturer Part Number=GJM0335C1E1R5WB01, Part number IPS=N.A., Part number NEMS=100200477, Supplier Part Number 1=490-11176-2-ND
C9: library part C0201-2.0p-HQ-Murata, "Capacitor, NP0, ±0.05pF, 25V", Manufacturer=Murata, Manufacturer Part Number=GJM0335C1E2R0WB01, Part number IPS=00000001775, Part number NEMS=100200419, Part number Norautron=N.A.
C11: library part C0201-0.3p-50V-GRM0335C1HR30BA01, "Capacitor, C0G, ±0.1pF, 50V", Manufacturer=Murata, Manufacturer Part Number=GRM0335C1HR30BA01, Part number IPS=N.A., Part number NEMS=100200650, Supplier Part Number 1=490-6135-2-ND
C12: library part C0201-18p, "Capacitor, C0G, ±5%, 25V", Manufacturer="Walsin Technology Corporation", Manufacturer Part Number=0201N180J250CT, Part number IPS=00000000862, Part number NEMS=100200035, Part number Norautron=26207023, Supplier Part Number 1=N.A.
C13: library part C0201-3.9p, "Chip Cap 0201", Manufacturer=N.A., Part number NEMS=100200024,100200424
C17 C19: library part C0402-TBD, "Chip Cap 0402", Manufacturer=N.A., Part number NEMS=100200106
C25 C28 C29: library part C0201-47p-25V-NP0-QLCD250Q470G1GV001T, "Capacitor, High Q, Low Loss, C0G/NP0, 25V, ±2%, -55°C ~ 125°C", Manufacturer="Johanson Technology", Manufacturer Part Number=QLCD250Q470G1GV001T, Part number IPS=00000010810, Part number Norautron=N.A., Supplier Part Number 1=712-QLCD250Q470G1GV001TCT-ND
C26: library part C0402-0.8p, "Capacitor, NP0, ±5%", Manufacturer=Murata, Manufacturer Part Number=GRM1555C1HR80WA01D, Part number IPS=00000007782, Part number NEMS=100200116, Part number Norautron=N.A., Supplier Part Number 1=490-6270-1-ND
C27 C31: library part C0402-N.C., "Not mounted", Manufacturer=N.A., Part number NEMS=100200105
C30: library part C0402-1.2p, "Capacitor, NP0, ±0.1pF", Manufacturer=N.A., Part number IPS=00000005410, Part number NEMS=100200119
C39: library part C0603-47µ, "Capacitor, X5R, ±20%, 6.3V", Manufacturer=N.A., Part number IPS=00000001818, Part number NEMS=100200277
C40: library part C0402-6.8p-50V-NP0-GJM1555C1H6R8BB01D, "Capacitor, High Q, Low Loss, C0G/NP0, 50V, ±0.1pF, -55°C ~ 125°C", Manufacturer=Murata, Manufacturer Part Number=GJM1555C1H6R8BB01D, Part number IPS=80000004966, Part number Norautron=N.A., Supplier Part Number 1=490-12599-1-ND
C41: library part C0402-2.0p-50V-NP0-GJM1555C1H2R0BB01, "Capacitor, High Q, Low Loss, C0G/NP0, 50V, ±0.1pF, -55°C ~ 125°C", Manufacturer=Murata, Manufacturer Part Number=GJM1555C1H2R0BB01, Part number IPS=80000004957, Part number NEMS=100200697, Part number Norautron=N.A., Supplier Part Number 1=490-8091-1-ND
C42: library part C0402-1.5p-50V-NP0-GJM1555C1H1R5BB01D, "Capacitor, High Q, Low Loss, C0G/NP0, 50V, ±0.1pF, -55°C ~ 125°C", Manufacturer=Murata, Manufacturer Part Number=GJM1555C1H1R5BB01D, Part number IPS=80000004967, Part number Norautron=N.A., Supplier Part Number 1=490-8087-1-ND
D1: "Zener Diode Array, 1 Pair, Common Anode, 12V, 265mW, ±5%", Manufacturer=Nexperia, Part number IPS=N.A., Part number NEMS=101300214, Supplier Part Number 1=1727-1585-1-ND
FB1 FB2: library part FB0201-120R@100M-200mA-BLM03AG121SN1D, "Ferrite Bead, 120 Ohm @ 100MHz, 200mA, 500 mOhm Max", Manufacturer=Murata, Manufacturer Part Number=BLM03AG121SN1D, Part number IPS=N.A., Part number NEMS=100300419, Supplier Part Number 1=490-5622-1-ND
Fid1 Fid2 Fid3: library part Fid-Mark, "Fiducial Mark", Manufacturer=N.A., Part number NEMS=100500073
L1: library part L0603-4µ7-MLZ1608M4R7WT000, "Inductor, 120mA, ±20%, 0.65R", Manufacturer="TDK Corporation", Manufacturer Part Number=MLZ1608M4R7WT000, Part number IPS=N.A., Part number NEMS=100300440, Supplier Part Number 1=445-6390-2-ND
L2: library part L0201-2n7-HQ-Murata, "Inductor, 600mA, ±0.1ｎH, 120mOhm", Manufacturer=Murata, Manufacturer Part Number=LQP03HQ2N7B02, Part number IPS=00000001753, Part number NEMS=100300214, Part number Norautron=N.A., Supplier Part Number 1=490-13909-1-ND
L3 L4: library part L0201-3n5-HQ-Murata, "Inductor, 500mA, ±0.1ｎH, 170mOhm", Manufacturer=Murata, Manufacturer Part Number=LQP03HQ3N5B02, Part number IPS=N.A., Part number NEMS=100300222, Supplier Part Number 1=490-13925-1-ND
L6: library part L1008-1m0-15mA-24Ω-LSQBA251818T102K, "Inductor, 15mA, ±10%, 24Ω", Manufacturer="Taiyo Yuden", Manufacturer Part Number=LSQBA251818T102K, Part number IPS=N.A., Part number NEMS=100300509, Supplier Part Number 1=587-LSQBA251818T102KCT-ND
L7: library part L0402-2n7-Multilayer_Murata, "Inductor, 800mA, ±2%, 120mΩ", Manufacturer=Murata, Manufacturer Part Number=LQG15HS2N7B02D, Part number IPS=N.A., Part number NEMS=100300445, Supplier Part Number 1=490-LQG15HS2N7B02DTR-ND
LABEL1: library part Label_8x8, "PCA version label, stick-on, 8x8mm", Manufacturer="Ellco Etikett", Manufacturer Part Number=A33511-01, Part number IPS=N.A., Part number NEMS=101200025
LED1 LED2: library part APHF1608LSEEQBDZGKC, "RGB LED 1.60 mm x 0.80 mm SMD", Manufacturer="Kingbright Company LLC", Part number IPS=00000001254, Part number NEMS=101400123, Part number Norautron=26470023, Supplier Part Number 1=754-2143-1-ND
LOGO1: library part "WEEE Symbol 3x4.5mm", "WEEE Directive symbol", Manufacturer=N.A., Part number NEMS=101100006
LOGO2: library part "Nordic Logo lying", "Nordic logo lying", Manufacturer=N.A., Part number NEMS=101100001
LOGO3: library part CE_logo, "CE (Conformité_Européenne) logo", Manufacturer=N.A., Part number NEMS=101100010
P1: library part "Socket 2x5, 1.27mm, Right Angle, TH", "Socket 2x5, 1.27mm (50mil), Right Angle, TH", Manufacturer=WCON, Manufacturer Part Number=2344-205RS0CUNR3, Part number IPS=N.A., Part number NEMS=100500894
P2: library part "Pin List 1x3, N.C.", "Pin List 1x3, 2.54mm (100mil)", Manufacturer=N.A., Part number NEMS=100500305
Q1: "Phototransistors 550nm Top View 0805 (2012 Metric)", Manufacturer=Vishay, Part number IPS=N.A., Part number NEMS=101400145, Supplier Part Number 1=751-1056-1-ND
Q2 Q3: "N-Channel MOSFET, 20V, 1A, 470mOhm, 400mW, -55°C ~ 150°C", Manufacturer="Rohm Semiconductor", Part number IPS=00000009976, Part number NEMS=101300132, Part number Norautron=26320026, Supplier Part Number 1=RV2C010UNT2LCT-ND
R1: library part R0201-1k0, "Resistor, ±1%, 0.05W", Manufacturer=N.A., Part number IPS=00000005786, Part number NEMS=100100043
R2 R3: library part R0201-10k, "Resistor, ±1%, 0.05W", Manufacturer=N.A., Part number IPS=00000001255, Part number NEMS=100100065, Part number Norautron=26107101
R4: library part R0201-2k7, "Resistor, ±1%, 0.05W", Manufacturer=N.A., Part number NEMS=100100054, Part number Norautron=26108481
R5: library part R0201-10R, "Resistor, ±1%, 0.05W", Manufacturer=N.A., Part number NEMS=100100014
R6: library part R0201-4R7, "Resistor, ±1%, 0.05W", Manufacturer=N.A., Part number IPS=00000002486, Part number NEMS=100100010
R8 R9: library part R0201-1M0, "Resistor, ±1%, 0.05W", Manufacturer=N.A., Part number IPS=00000001418, Part number NEMS=100100093, Part number Norautron=26107108
R11 R14: library part R0201-390, "Resistor, ±1%, 0.05W", Manufacturer=N.A., Part number IPS=00000001258, Part number NEMS=100100035, Part number Norautron=26470031
R12 R15: library part R0201-2k2, "Resistor, ±1%, 0.05W", Manufacturer=N.A., Part number IPS=00000001257, Part number NEMS=100100052, Part number Norautron=26470030
R13 R16: library part R0201-1k2, "Resistor, ±1%, 0.05W", Manufacturer=N.A., Part number IPS=00000001256, Part number NEMS=100100045, Part number Norautron=26107084
R17: library part R0201-100k, "Resistor, ±1%, 0.05W", Manufacturer=N.A., Part number IPS=00000001419, Part number NEMS=100100080, Part number Norautron=26108487
R19: library part R0201-0R, "Resistor, ±5%, 0.05W", Manufacturer=N.A., Part number IPS=00000003245, Part number NEMS=100100001
SB1: library part "Solderbridge Shorted Power", "Shorted Solderbridge Power", Manufacturer=N.A., Part number NEMS=100500460
SW1: library part L-KLS7-TS3402-2.5-250-B-T, "Tactile Switch, SPNO, SMD, 260gf, 4.2x3.3x2.5mm", Manufacturer="KLS Electronic", Part number IPS=N.A., Part number NEMS=101500152
SW2 SW3: library part "KMT021 NGJ LHS", "Nano-Miniature Top Actuated Tact Switch with extended life 3.0x2.6mm", Manufacturer=C&K, Part number IPS=00000005416, Part number NEMS=101500039, Part number Norautron=N.A., Supplier Part Number 1=CKN10289CT-ND
TP1 TP2 TP3 TP4 TP5 TP6 TP7: library part TP_SMD_Ø1.5MM, "1.5mm circular SMD testpad", Manufacturer="Nordic Semiconductor", Manufacturer Part Number=N.A., Part number NEMS=100500477
TP12 TP13: library part TP_SMD_Ø1.0MM, "1.0mm circular SMD testpad", Manufacturer="Nordic Semiconductor", Manufacturer Part Number=N.A., Part number NEMS=100500475
U1: "Multi-protocol Bluetooth Low Energy, IEEE 802.15.4 and 2.4GHz proprietary Wireless MCU", Manufacturer="Nordic Semiconductor", Part number IPS=N.A., Part number NEMS=102000382
U3: "Low power gas, pressure, temperature & humidity sensor", Manufacturer=Bosch, Part number IPS=N.A., Part number NEMS=101900619, Supplier Part Number 1=828-BME688TR-ND
U4: "6-axis, smart, low-power, inertial measurement unit", Manufacturer=Bosch, Part number IPS=N.A., Part number NEMS=101900620, Supplier Part Number 1=828-1091-1-ND
U5: library part ADXL367BCCZ, "Micropower, 3-Axis, ±2 g/±4 g/±8 g Digital Output MEMS Accelerometer", Manufacturer="Analog Devices", Part number IPS=N.A., Part number NEMS=101900775, Supplier Part Number 1=505-ADXL367BCCZ-RL7CT-ND
U6: "50 MHz-6.0 GHz GaAs SPDT Switch", Manufacturer=Skyworks, Part number IPS=N.A., Part number NEMS=101900872, Supplier Part Number 1=863-1335-1-ND
U8: library part MX25R6435FZBIH3, "Ultra low power, 64M-bit, serial multi I/O flash memory", Manufacturer=Macronix, Part number IPS=N.A., Part number NEMS=101900860, Supplier Part Number 1=1092-MX25R6435FZBIH3CT-ND
X1: library part XTAL_SMD2012_32.768kHz_9pF_TXC, "XTAL SMD 2012, 32.768kHz, 9pF, ±20ppm", Manufacturer="TXC Corporation", Manufacturer Part Number=9HT11-32.768KDZC-T, Part number IPS=N.A., Part number NEMS=101600107, Supplier Part Number 1=887-1426-2-ND
X2: library part XTAL_SMD2016_32MHz_8pF_Kyocera, "XTAL SMD 2016, 32MHz, Cl=8pF, Tot: ±40ppm", Manufacturer=Kyocera, Manufacturer Part Number=CX2016DB32000D0WZRC1, Part number IPS=00000007827, Part number NEMS=101600039, Part number Norautron=26511136, Supplier Part Number 1=1253-1586-1-ND

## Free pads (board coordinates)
  round 0.4 hole 0.4 unplated: 0(-14.042,-8.946) 0(-14.042,8.946) 0(-13.639,-9.55) 0(-13.639,9.55) 0(-13.209,-10.136) 0(-13.209,10.136) 0(-12.755,-10.702) 0(-12.755,10.702) 0(-12.276,-11.249) 0(-12.276,11.249) 0(12.276,-11.249) 0(12.276,11.249) 0(12.755,-10.702) 0(12.755,10.702) 0(13.209,-10.136) 0(13.209,10.136) 0(13.639,-9.55) 0(13.639,9.55) 0(14.042,-8.946) 0(14.042,8.946)

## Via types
v1: diameter 0.5, hole 0.25, Top Layer to Bottom Layer, tented both sides, 369 vias

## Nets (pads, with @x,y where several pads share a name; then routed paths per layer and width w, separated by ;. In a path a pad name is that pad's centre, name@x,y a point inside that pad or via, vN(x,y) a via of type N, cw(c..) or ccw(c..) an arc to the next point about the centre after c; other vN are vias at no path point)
ANT1: C29.1 C30.2 L7.1 | length 7.1
  Top Layer w0.517: L7.1@11.729,8.525 cw(c0,0) C29.1@14.364,1.985
ANT2: C25.1 C26.2 C40.1 | length 7.1
  Top Layer w0.517: C40.1@11.729,-8.525 ccw(c0,0) C25.1@14.364,-1.985
DCC: L1.1 U1.46 | length 2.8
  Top Layer w0.2: L1.1@0.248,5.028 0.248,5.003 0.523,4.728 0.766,4.728 1.101,4.393 1.101,4.088 1.228,3.961 1.228,3.456 1.4,3.284 U1.46@1.4,2.825
DECA: C2.2 C12.2 FB1.2 FB2.2 R6.2 U1.43 | length 10.2
  Top Layer w0.2: U1.43@2.6,2.825 2.6,3.474 C12.2@2.828,3.702 2.863,3.737 3.05,3.737 v1@3.488,4.175 ; FB1.2@2.828,5.302 C2.2@3.388,5.302 3.388,4.349 3.488,4.249 v1(3.488,4.168)
  Bottom Layer w0.3: v1(3.488,4.168) 3.542,4.168 4.036,3.675 8.085,3.675 FB2.2@8.975,2.785 R6.2@9.575,2.785
DECD: C1.2 FB1.1 L1.2 U1.45 | length 5.4
  Top Layer w0.2: L1.2@1.609,5.068 v1(1.609,4.292) 1.609,3.73 C1.2@1.63,3.709 1.63,3.694 1.665,3.659 1.68,3.659 1.8,3.539 1.8,3.05 U1.45@1.8,2.825 ; v1(2.3,6.4) 2.778,5.922 2.778,5.907 2.813,5.872 FB1.1@2.828,5.872
  Mid-Layer 2 w0.2: v1(1.609,4.292) 1.609,5.584 v1@2.3,6.275
DECRF: C5.2 FB2.1 R6.1 U1.33 | length 4.5
  Top Layer w0.2: U1.33@5.825,0.8 6.288,0.8 6.457,0.969 6.648,0.969 6.683,1.004 C5.2@6.683,1.019 ; C5.2@6.683,1.015 6.718,1.05 6.718,1.245 6.989,1.516 7.215,1.516 v1(7.273,1.574)
  Bottom Layer w0.3: v1(7.273,1.574) 7.914,2.215 R6.1@9.575,2.215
